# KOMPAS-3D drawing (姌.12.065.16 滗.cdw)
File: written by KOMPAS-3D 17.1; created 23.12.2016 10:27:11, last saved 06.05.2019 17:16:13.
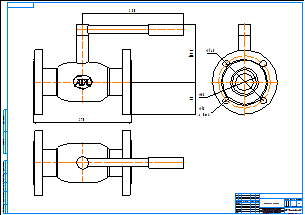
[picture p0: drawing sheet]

Sheet 1: A1, landscape

Title block, sheet 1: name: КШ.12.065.16 фф; material: Внимание! Данный продукт является объектом авторского права ООО «Торговый Дом АДЛ». / Запрещается изменение, копирование, распространение / (в том числе путем копирования на другие сайты и ресурсы в Интернете) / или любое иное использование информации и объектов без предварительного / согласия правообладателя (ООО «Торговый Дом АДЛ»).; sheets: 1; organisation: ООО "Торговый дом АДЛ"; sheet format: A1; stored path: C:\Users\tra\Desktop\2д чертежи\Шаровые краны БИВАЛ\КШ_Бивал_серия_11_12\KOMPAS_2D\КШ.12.065.16 фф.cdw

Views: Вид 1, Проекционный вид 2, Проекционный вид 3
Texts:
  Klimkovich
  ADL
Dimensions and other numbers on the sheet: 270; 280; 159,3; 90; 145; 68; 18; 4 Отв.; 1:1; 1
